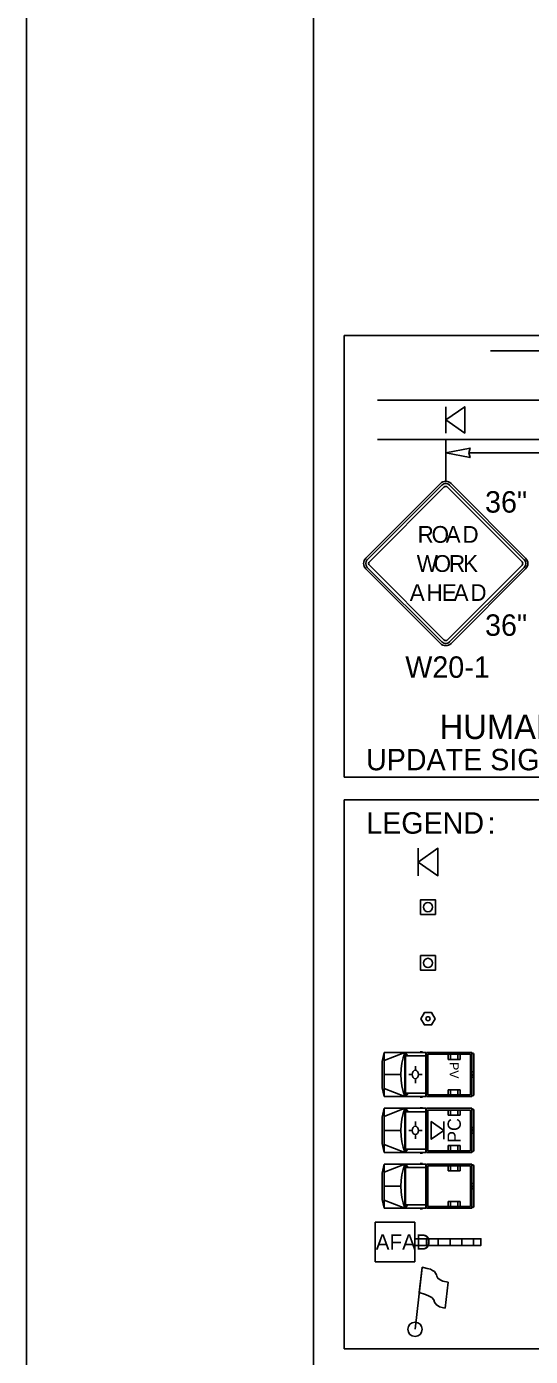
# Model space of a CAD drawing. Extents: x 99999.1 to 100095.7, y 99995 to 100010.7.
# Drawn here: x 100039.062 to 100040.708, y 100001.151 to 100005.492 of the extents above; entities that cross this region are included whole.
import ezdxf

# ---------------------------------------------------------------- set-up
doc = ezdxf.new("R2010")
doc.units = 0
for name, color, linetype in [('RD_ED_ShoulderPavedEdge', 7, 'Continuous'), ('RD_MK_LineEdgeWhite', 7, 'Continuous'), ('SH_DE_DetailHeading2Text', 7, 'Continuous'), ('SH_GI_PlotLimits', 7, 'Continuous'), ('SH_GI_SheetBorder', 7, 'Continuous'), ('TR_SN_ConstructionSigns', 7, 'Continuous'), ('TR_WZ_AFAD', 7, 'Continuous'), ('TR_WZ_FlaggingStation', 7, 'Continuous'), ('TR_WZ_MotoristVehicle', 7, 'Continuous'), ('TR_WZ_PortableSignMountBlk-Org', 7, 'Continuous'), ('TR_WZ_PortableSignMountBlk-Wht', 7, 'Continuous'), ('TR_WZ_ProtectiveVehicle', 7, 'Continuous'), ('TR_WZ_TrafficCone', 7, 'Continuous'), ('TR_WZ_TubularMarker', 7, 'Continuous'), ('TR_WZ_WorkZoneDetails', 7, 'Continuous'), ('TR_WZ_WorkZoneTextCurrent', 7, 'Continuous')]:
    doc.layers.add(name, color=color, linetype=linetype)

msp = doc.modelspace()

# ---------------------------------------------------------------- linework, layer by layer
at = {"layer": 'RD_ED_ShoulderPavedEdge'}
msp.add_line((100040.2089, 100004.1438), (100043.1825, 100004.1438), dxfattribs=at)
at = {"layer": 'RD_MK_LineEdgeWhite'}
msp.add_line((100040.2089, 100004.273), (100043.1825, 100004.273), dxfattribs=at)
at = {"layer": 'SH_GI_PlotLimits'}
msp.add_lwpolyline([(100039.0625, 99999.6875), (100056.0625, 99999.6875), (100056.0625, 100010.6875), (100039.0625, 100010.6875)], close=True, dxfattribs=at)
at = {"layer": 'SH_GI_SheetBorder'}
msp.add_line((100040, 100010.375), (100040, 100000), dxfattribs=at)
at = {"layer": 'TR_SN_ConstructionSigns'}
for p, q in [((100040.4143, 100004.0005), (100040.1706, 100003.7569)), ((100040.4191, 100003.9957), (100040.1755, 100003.752)), ((100040.1822, 100003.7453), (100040.4259, 100003.9889)), ((100040.4375, 100003.9889), (100040.6811, 100003.7453)), ((100040.6879, 100003.752), (100040.4442, 100003.9957)), ((100040.6927, 100003.7569), (100040.4491, 100004.0005)), ((100040.1706, 100003.7221), (100040.4143, 100003.4785)), ((100040.1755, 100003.7269), (100040.4191, 100003.4833)), ((100040.4259, 100003.4901), (100040.1822, 100003.7337)), ((100040.6811, 100003.7337), (100040.4375, 100003.4901)), ((100040.4442, 100003.4833), (100040.6879, 100003.7269)), ((100040.4491, 100003.4785), (100040.6927, 100003.7221))]:
    msp.add_line(p, q, dxfattribs=at)
for centre, radius, start, end in [((100040.4317, 100003.9831), 0.0246, 45, 135), ((100040.4317, 100003.9831), 0.0178, 45, 135), ((100040.4317, 100003.9831), 0.0082, 45, 135), ((100040.188, 100003.7395), 0.0246, 135, 225), ((100040.188, 100003.7395), 0.0178, 135, 225), ((100040.188, 100003.7395), 0.0082, 135, 225), ((100040.6753, 100003.7395), 0.0082, 315, 45), ((100040.6753, 100003.7395), 0.0178, 315, 45), ((100040.6753, 100003.7395), 0.0246, 315, 45), ((100040.4317, 100003.4959), 0.0178, 225, 315), ((100040.4317, 100003.4959), 0.0082, 225, 315), ((100040.4317, 100003.4959), 0.0246, 225, 315)]:
    msp.add_arc(centre, radius, start, end, dxfattribs=at)
at = {"layer": 'TR_WZ_AFAD'}
for p, q in [((100040.2009, 100001.4595), (100040.2009, 100001.5891)), ((100040.2009, 100001.5891), (100040.3305, 100001.5891)), ((100040.3305, 100001.5891), (100040.2009, 100001.5891)), ((100040.2009, 100001.5891), (100040.2009, 100001.4595)), ((100040.3305, 100001.5891), (100040.3305, 100001.4595)), ((100040.3305, 100001.5291), (100040.3305, 100001.5891)), ((100040.3689, 100001.5351), (100040.3305, 100001.5351)), ((100040.3305, 100001.5351), (100040.3305, 100001.5291)), ((100040.3305, 100001.5291), (100040.3305, 100001.5243)), ((100040.4073, 100001.5351), (100040.3689, 100001.5351)), ((100040.4457, 100001.5351), (100040.4073, 100001.5351)), ((100040.4073, 100001.5243), (100040.4073, 100001.5351)), ((100040.4841, 100001.5351), (100040.4457, 100001.5351)), ((100040.4457, 100001.5351), (100040.4457, 100001.5243)), ((100040.5225, 100001.5351), (100040.4841, 100001.5351)), ((100040.4841, 100001.5243), (100040.4841, 100001.5351)), ((100040.5225, 100001.5351), (100040.5225, 100001.5243)), ((100040.3689, 100001.5135), (100040.4073, 100001.5135)), ((100040.4073, 100001.5135), (100040.4073, 100001.5243)), ((100040.4073, 100001.5135), (100040.4457, 100001.5135)), ((100040.4457, 100001.5243), (100040.4457, 100001.5135)), ((100040.4457, 100001.5135), (100040.4841, 100001.5135)), ((100040.4841, 100001.5135), (100040.4841, 100001.5243)), ((100040.4841, 100001.5135), (100040.5225, 100001.5135)), ((100040.5225, 100001.5243), (100040.5225, 100001.5135)), ((100040.5225, 100001.5135), (100040.5465, 100001.5135)), ((100040.3305, 100001.4595), (100040.2009, 100001.4595)), ((100040.2009, 100001.4595), (100040.3305, 100001.4595))]:
    msp.add_line(p, q, dxfattribs=at)
for points in [[(100040.3305, 100001.5135), (100040.5465, 100001.5135), (100040.5465, 100001.5351), (100040.3305, 100001.5351)], [(100040.3305, 100001.4595), (100040.3305, 100001.5195), (100040.3305, 100001.5291)], [(100040.3689, 100001.5135), (100040.3689, 100001.5243), (100040.3689, 100001.5351)], [(100040.3689, 100001.5351), (100040.3689, 100001.5243), (100040.3689, 100001.5135)], [(100040.4073, 100001.5351), (100040.4073, 100001.5243), (100040.4073, 100001.5135)], [(100040.4457, 100001.5135), (100040.4457, 100001.5243), (100040.4457, 100001.5351)], [(100040.4841, 100001.5351), (100040.4841, 100001.5243), (100040.4841, 100001.5135)], [(100040.5225, 100001.5135), (100040.5225, 100001.5243), (100040.5225, 100001.5351)], [(100040.5465, 100001.5135), (100040.5465, 100001.5351), (100040.5225, 100001.5351)], [(100040.3305, 100001.5243), (100040.3305, 100001.5195), (100040.3305, 100001.5135), (100040.3689, 100001.5135)]]:
    msp.add_lwpolyline(points, dxfattribs=at)
at = {"layer": 'TR_WZ_FlaggingStation'}
for p, q in [((100040.3314, 100001.2393), (100040.3545, 100001.4416)), ((100040.3451, 100001.3595), (100040.3545, 100001.4418)), ((100040.3451, 100001.3595), (100040.3451, 100001.3595)), ((100040.4394, 100001.393), (100040.4299, 100001.3086))]:
    msp.add_line(p, q, dxfattribs=at)
for points in [[(100040.3545, 100001.4418), (100040.3586, 100001.4409), (100040.3715, 100001.4384), (100040.3814, 100001.4354), (100040.3884, 100001.431), (100040.3945, 100001.4276), (100040.3986, 100001.4227), (100040.4017, 100001.4171), (100040.4021, 100001.4126), (100040.4059, 100001.406), (100040.4137, 100001.4006), (100040.4226, 100001.3969), (100040.4394, 100001.393)], [(100040.4299, 100001.3086), (100040.424, 100001.3096), (100040.4112, 100001.313), (100040.4, 100001.3205), (100040.3953, 100001.3281), (100040.3925, 100001.3355), (100040.3859, 100001.3434), (100040.378, 100001.3479), (100040.3655, 100001.353), (100040.3451, 100001.3595)]]:
    msp.add_lwpolyline(points, dxfattribs=at)
msp.add_circle((100040.3314, 100001.2393), 0.0234, dxfattribs=at)
at = {"layer": 'TR_WZ_MotoristVehicle'}
for p, q in [((100040.348, 100001.9628), (100040.3562, 100001.9628)), ((100040.2305, 100001.9608), (100040.2239, 100001.9317)), ((100040.2239, 100001.9317), (100040.2239, 100001.8458)), ((100040.2305, 100001.9608), (100040.2305, 100001.8168)), ((100040.2305, 100001.9608), (100040.3665, 100001.9608)), ((100040.2305, 100001.9344), (100040.2985, 100001.9608)), ((100040.2985, 100001.9608), (100040.2985, 100001.8168)), ((100040.2998, 100001.9608), (100040.2998, 100001.8168)), ((100040.2998, 100001.9608), (100040.3084, 100001.9496)), ((100040.2998, 100001.9496), (100040.3665, 100001.9496)), ((100040.3665, 100001.9608), (100040.3665, 100001.8168)), ((100040.5166, 100001.9608), (100040.3685, 100001.9608)), ((100040.3685, 100001.9608), (100040.3685, 100001.8168)), ((100040.5124, 100001.955), (100040.3727, 100001.955)), ((100040.3727, 100001.955), (100040.3727, 100001.8225)), ((100040.4395, 100001.955), (100040.4395, 100001.9385)), ((100040.4791, 100001.9385), (100040.4395, 100001.9385)), ((100040.4467, 100001.955), (100040.4467, 100001.9385)), ((100040.4711, 100001.955), (100040.4711, 100001.9385)), ((100040.4791, 100001.955), (100040.4791, 100001.9385)), ((100040.5124, 100001.955), (100040.5124, 100001.8225)), ((100040.5166, 100001.9608), (100040.5166, 100001.8168)), ((100040.5204, 100001.9584), (100040.5171, 100001.9584)), ((100040.5171, 100001.9584), (100040.5171, 100001.8191)), ((100040.5236, 100001.954), (100040.5236, 100001.8235)), ((100040.2305, 100001.8888), (100040.2852, 100001.8888)), ((100040.3107, 100001.8889), (100040.3198, 100001.8888)), ((100040.3324, 100001.9173), (100040.3324, 100001.9057)), ((100040.3426, 100001.8885), (100040.3426, 100001.8885)), ((100040.3546, 100001.8882), (100040.3439, 100001.8885)), ((100040.5236, 100001.8989), (100040.5171, 100001.8962)), ((100040.5236, 100001.8786), (100040.5171, 100001.8813)), ((100040.5218, 100001.8888), (100040.5189, 100001.8888)), ((100040.5204, 100001.8908), (100040.5204, 100001.8867)), ((100040.2305, 100001.8168), (100040.2239, 100001.8458)), ((100040.2305, 100001.8431), (100040.2985, 100001.8168)), ((100040.3329, 100001.8611), (100040.3327, 100001.8719)), ((100040.4395, 100001.8225), (100040.4395, 100001.8391)), ((100040.4791, 100001.8391), (100040.4395, 100001.8391)), ((100040.4467, 100001.8225), (100040.4467, 100001.8391)), ((100040.4711, 100001.8225), (100040.4711, 100001.8391)), ((100040.4791, 100001.8225), (100040.4791, 100001.8391)), ((100040.2305, 100001.8168), (100040.3665, 100001.8168)), ((100040.2998, 100001.8279), (100040.3665, 100001.8279)), ((100040.3069, 100001.8279), (100040.2998, 100001.8168)), ((100040.348, 100001.8147), (100040.3562, 100001.8147)), ((100040.5166, 100001.8168), (100040.3685, 100001.8168)), ((100040.5124, 100001.8225), (100040.3727, 100001.8225)), ((100040.5204, 100001.8191), (100040.5171, 100001.8191)), ((100040.2305, 100001.7785), (100040.2239, 100001.7494)), ((100040.2239, 100001.7494), (100040.2239, 100001.6636)), ((100040.2305, 100001.7785), (100040.2305, 100001.6345)), ((100040.2305, 100001.7785), (100040.3665, 100001.7785)), ((100040.2305, 100001.7521), (100040.2985, 100001.7785)), ((100040.2985, 100001.7785), (100040.2985, 100001.6345)), ((100040.2998, 100001.7785), (100040.2998, 100001.6345)), ((100040.2998, 100001.7785), (100040.3084, 100001.7674)), ((100040.2998, 100001.7674), (100040.3665, 100001.7674)), ((100040.348, 100001.7805), (100040.3562, 100001.7805)), ((100040.3665, 100001.7785), (100040.3665, 100001.6345)), ((100040.5166, 100001.7785), (100040.3685, 100001.7785)), ((100040.3685, 100001.7785), (100040.3685, 100001.6345)), ((100040.5124, 100001.7728), (100040.3727, 100001.7728)), ((100040.3727, 100001.7728), (100040.3727, 100001.6403)), ((100040.4395, 100001.7728), (100040.4395, 100001.7562)), ((100040.4791, 100001.7562), (100040.4395, 100001.7562)), ((100040.4467, 100001.7728), (100040.4467, 100001.7562)), ((100040.4711, 100001.7728), (100040.4711, 100001.7562)), ((100040.4791, 100001.7728), (100040.4791, 100001.7562)), ((100040.5124, 100001.7728), (100040.5124, 100001.6403)), ((100040.5166, 100001.7785), (100040.5166, 100001.6345)), ((100040.5204, 100001.7761), (100040.5171, 100001.7761)), ((100040.5171, 100001.7761), (100040.5171, 100001.6369)), ((100040.5236, 100001.7718), (100040.5236, 100001.6413)), ((100040.2305, 100001.7065), (100040.2852, 100001.7065)), ((100040.5236, 100001.7167), (100040.5171, 100001.714)), ((100040.5218, 100001.7065), (100040.5189, 100001.7065)), ((100040.5204, 100001.7085), (100040.5204, 100001.7045)), ((100040.2305, 100001.6345), (100040.2239, 100001.6636)), ((100040.2305, 100001.6609), (100040.2985, 100001.6345)), ((100040.5236, 100001.6964), (100040.5171, 100001.6991)), ((100040.2305, 100001.6345), (100040.3665, 100001.6345)), ((100040.2998, 100001.6457), (100040.3665, 100001.6457)), ((100040.3069, 100001.6457), (100040.2998, 100001.6345)), ((100040.348, 100001.6325), (100040.3562, 100001.6325)), ((100040.5166, 100001.6345), (100040.3685, 100001.6345)), ((100040.5124, 100001.6403), (100040.3727, 100001.6403)), ((100040.4395, 100001.6403), (100040.4395, 100001.6568)), ((100040.4791, 100001.6568), (100040.4395, 100001.6568)), ((100040.4467, 100001.6403), (100040.4467, 100001.6568)), ((100040.4711, 100001.6403), (100040.4711, 100001.6568)), ((100040.4791, 100001.6403), (100040.4791, 100001.6568)), ((100040.5204, 100001.6369), (100040.5171, 100001.6369))]:
    msp.add_line(p, q, dxfattribs=at)
for centre, major_axis, start_param, end_param in [((100040.3957, 100001.8887), (0, -0.1511), 4.215667, 5.208926), ((100040.5204, 100001.954), (0, 0.00439), 4.712389, 6.283185), ((100040.5204, 100001.8235), (0, -0.00439), 0, 1.570796), ((100040.3957, 100001.7065), (0, -0.1511), 4.215667, 5.208926), ((100040.5204, 100001.7718), (0, 0.00439), 4.712389, 6.283185), ((100040.5204, 100001.6413), (0, -0.00439), 0, 1.570796)]:
    msp.add_ellipse(centre, major_axis=major_axis, ratio=0.73155, start_param=start_param, end_param=end_param, dxfattribs=at)
for centre, major_axis in [((100040.3324, 100001.8888), (0, 0.0139)), ((100040.5204, 100001.8888), (0, 0.00203)), ((100040.5204, 100001.7065), (0, 0.00203))]:
    msp.add_ellipse(centre, major_axis=major_axis, ratio=0.73155, dxfattribs=at)
at = {"layer": 'TR_WZ_PortableSignMountBlk-Org'}
for p, q in [((100040.4317, 100004.1654), (100040.4317, 100004.2515)), ((100040.3414, 100002.72), (100040.3414, 100002.81))]:
    msp.add_line(p, q, dxfattribs=at)
for points in [[(100040.4317, 100004.2084), (100040.4935, 100004.2515), (100040.4935, 100004.1654)], [(100040.3414, 100002.7649), (100040.406, 100002.81), (100040.406, 100002.72)]]:
    msp.add_lwpolyline(points, close=True, dxfattribs=at)
at = {"layer": 'TR_WZ_PortableSignMountBlk-Wht'}
msp.add_line((100040.4259, 100001.9175), (100040.4259, 100001.8599), dxfattribs=at)
msp.add_lwpolyline([(100040.4259, 100001.8887), (100040.3845, 100001.8599), (100040.3845, 100001.9175)], close=True, dxfattribs=at)
at = {"layer": 'TR_WZ_ProtectiveVehicle'}
for p, q in [((100040.2305, 100002.143), (100040.2239, 100002.1139)), ((100040.2305, 100001.999), (100040.2305, 100002.143)), ((100040.2305, 100002.143), (100040.3665, 100002.143)), ((100040.2305, 100002.1166), (100040.2985, 100002.143)), ((100040.2985, 100001.999), (100040.2985, 100002.143)), ((100040.2998, 100001.999), (100040.2998, 100002.143)), ((100040.3069, 100002.1319), (100040.2998, 100002.143)), ((100040.348, 100002.145), (100040.3562, 100002.145)), ((100040.3665, 100001.999), (100040.3665, 100002.143)), ((100040.5166, 100002.143), (100040.3685, 100002.143)), ((100040.3685, 100001.999), (100040.3685, 100002.143)), ((100040.5124, 100002.1373), (100040.3727, 100002.1373)), ((100040.3727, 100002.0048), (100040.3727, 100002.1373)), ((100040.4395, 100002.1373), (100040.4395, 100002.1207)), ((100040.4467, 100002.1373), (100040.4467, 100002.1207)), ((100040.4711, 100002.1373), (100040.4711, 100002.1207)), ((100040.4791, 100002.1373), (100040.4791, 100002.1207)), ((100040.5124, 100002.0048), (100040.5124, 100002.1373)), ((100040.5166, 100001.999), (100040.5166, 100002.143)), ((100040.5204, 100002.1406), (100040.5171, 100002.1406)), ((100040.5171, 100002.0014), (100040.5171, 100002.1406)), ((100040.5236, 100002.0058), (100040.5236, 100002.1362)), ((100040.2239, 100002.0281), (100040.2239, 100002.1139)), ((100040.2998, 100002.1319), (100040.3665, 100002.1319)), ((100040.3329, 100002.0987), (100040.3327, 100002.0879)), ((100040.4791, 100002.1207), (100040.4395, 100002.1207)), ((100040.2305, 100002.071), (100040.2852, 100002.071)), ((100040.3107, 100002.0709), (100040.3198, 100002.071)), ((100040.3324, 100002.0425), (100040.3324, 100002.0541)), ((100040.3426, 100002.0713), (100040.3426, 100002.0713)), ((100040.3546, 100002.0716), (100040.3439, 100002.0713)), ((100040.5236, 100002.0811), (100040.5171, 100002.0784)), ((100040.5236, 100002.0609), (100040.5171, 100002.0636)), ((100040.5218, 100002.071), (100040.5189, 100002.071)), ((100040.5204, 100002.069), (100040.5204, 100002.073)), ((100040.2305, 100001.999), (100040.2239, 100002.0281)), ((100040.2305, 100002.0254), (100040.2985, 100001.999)), ((100040.2998, 100001.999), (100040.3084, 100002.0102)), ((100040.2998, 100002.0102), (100040.3665, 100002.0102)), ((100040.4791, 100002.0213), (100040.4395, 100002.0213)), ((100040.4395, 100002.0048), (100040.4395, 100002.0213)), ((100040.4467, 100002.0048), (100040.4467, 100002.0213)), ((100040.4711, 100002.0048), (100040.4711, 100002.0213)), ((100040.4791, 100002.0048), (100040.4791, 100002.0213)), ((100040.2305, 100001.999), (100040.3665, 100001.999)), ((100040.348, 100001.997), (100040.3562, 100001.997)), ((100040.5166, 100001.999), (100040.3685, 100001.999)), ((100040.5124, 100002.0048), (100040.3727, 100002.0048)), ((100040.5204, 100002.0014), (100040.5171, 100002.0014))]:
    msp.add_line(p, q, dxfattribs=at)
for centre, major_axis, start_param, end_param in [((100040.3957, 100002.071), (0, -0.1511), 4.215852, 5.209111), ((100040.5204, 100002.1362), (0, 0.00439), 4.712389, 6.283185), ((100040.5204, 100002.0058), (0, -0.00439), 6.283185, 7.853982)]:
    msp.add_ellipse(centre, major_axis=major_axis, ratio=0.73155, start_param=start_param, end_param=end_param, dxfattribs=at)
for centre, major_axis in [((100040.3324, 100002.071), (0, 0.0139)), ((100040.5204, 100002.071), (0, 0.00203))]:
    msp.add_ellipse(centre, major_axis=major_axis, ratio=0.73155, dxfattribs=at)
at = {"layer": 'TR_WZ_TrafficCone'}
for points in [[(100040.3497, 100002.6417), (100040.3977, 100002.6417), (100040.3977, 100002.5937), (100040.3497, 100002.5937), (100040.3497, 100002.6417)], [(100040.3497, 100002.5937), (100040.3977, 100002.5937), (100040.3977, 100002.6417), (100040.3497, 100002.6417), (100040.3497, 100002.5937)], [(100040.3497, 100002.4595), (100040.3977, 100002.4595), (100040.3977, 100002.4115), (100040.3497, 100002.4115), (100040.3497, 100002.4595)], [(100040.3497, 100002.4115), (100040.3977, 100002.4115), (100040.3977, 100002.4595), (100040.3497, 100002.4595), (100040.3497, 100002.4115)]]:
    msp.add_lwpolyline(points, dxfattribs=at)
for centre in [(100040.3737, 100002.6177), (100040.3737, 100002.4355)]:
    msp.add_circle(centre, 0.015, dxfattribs=at)
at = {"layer": 'TR_WZ_TubularMarker'}
msp.add_lwpolyline([(100040.3506, 100002.2533), (100040.3622, 100002.2733), (100040.3853, 100002.2733), (100040.3968, 100002.2533), (100040.3853, 100002.2333), (100040.3622, 100002.2333)], close=True, dxfattribs=at)
msp.add_lwpolyline([(100040.3622, 100002.2333), (100040.3853, 100002.2333), (100040.3968, 100002.2533), (100040.3853, 100002.2733), (100040.3622, 100002.2733), (100040.3506, 100002.2533), (100040.3622, 100002.2333)], dxfattribs=at)
msp.add_circle((100040.3737, 100002.2533), 0.00667, dxfattribs=at)
at = {"layer": 'TR_WZ_WorkZoneDetails'}
for p, q in [((100040.7726, 100004.4337), (100040.578, 100004.4337)), ((100040.4317, 100004.144), (100040.4317, 100004.0077)), ((100041.0019, 100004.1008), (100040.5073, 100004.1008))]:
    msp.add_line(p, q, dxfattribs=at)
msp.add_lwpolyline([(100040.4317, 100004.1008), (100040.511, 100004.1163), (100040.5073, 100004.1008), (100040.511, 100004.0852)], close=True, dxfattribs=at)
at = {"layer": 'TR_WZ_WorkZoneTextCurrent'}
for points in [[(100040.1, 100004.4837), (100043.2886, 100004.4837), (100043.2886, 100003.0424), (100040.1, 100003.0424)], [(100040.1, 100002.9674), (100043.2886, 100002.9674), (100043.2886, 100001.1759), (100040.1, 100001.1759)]]:
    msp.add_lwpolyline(points, close=True, dxfattribs=at)

# ---------------------------------------------------------------- texts
at = {"layer": 'SH_DE_DetailHeading2Text'}
msp.add_text('HUMAN FLAGGER SUBSTITUTION', height=0.08, rotation=360, dxfattribs=at).set_placement((100040.4115, 100003.1664))
at = {"layer": 'TR_SN_ConstructionSigns'}
for s, p in [('36"', (100040.5601, 100003.9056)), ('36"', (100040.5601, 100003.5034)), ('W20-1', (100040.2996, 100003.3663))]:
    msp.add_text(s, height=0.07, rotation=360, dxfattribs=at).set_placement(p)
for s, p in [('R', (100040.3397, 100003.8071)), ('O', (100040.3854, 100003.8071)), ('A', (100040.4315, 100003.8071)), ('D', (100040.4864, 100003.8071)), ('W', (100040.3369, 100003.7121)), ('O', (100040.3922, 100003.7121)), ('R', (100040.4423, 100003.7121)), ('K', (100040.4882, 100003.7121)), ('A', (100040.3141, 100003.6172)), ('H', (100040.3688, 100003.6172)), ('E', (100040.4191, 100003.6172)), ('A', (100040.4574, 100003.6172)), ('D', (100040.5121, 100003.6172))]:
    msp.add_text(s, height=0.0547, dxfattribs=at).set_placement(p)
at = {"layer": 'TR_WZ_AFAD'}
msp.add_text('AFAD', height=0.0504, dxfattribs=at).set_placement((100040.203, 100001.4991))
at = {"layer": 'TR_WZ_MotoristVehicle'}
msp.add_text('PC', height=0.0432, rotation=90, dxfattribs=at).set_placement((100040.4809, 100001.8484))
at = {"layer": 'TR_WZ_ProtectiveVehicle'}
msp.add_text('PV', height=0.03006, rotation=270, dxfattribs=at).set_placement((100040.4442, 100002.1118))
at = {"layer": 'TR_WZ_WorkZoneTextCurrent'}
msp.add_text('UPDATE SIGNAGE & USE STOP/SLOW PADDLE', height=0.07, dxfattribs=at).set_placement((100040.1713, 100003.0644))
for s, p in [('LEGEND', (100040.172, 100002.8574)), (':', (100040.5682, 100002.8574))]:
    msp.add_text(s, height=0.07, rotation=360, dxfattribs=at).set_placement(p)

doc.saveas('drawing.dxf')
